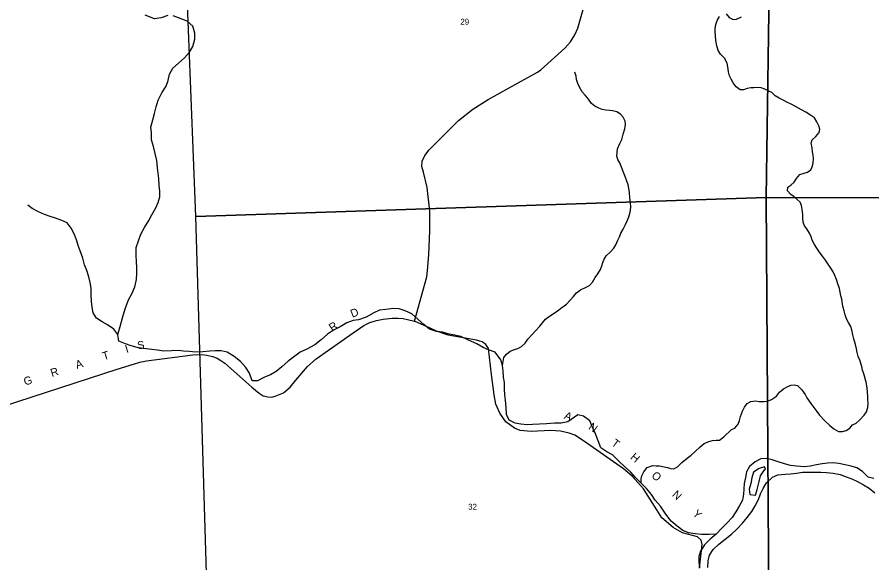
# Model space of a CAD drawing. Extents: x 1312308 to 1684953, y 460642 to 865172.
# Drawn here: x 1414861 to 1422870, y 611344 to 616453 of the extents above; entities that cross this region are included whole.
import ezdxf

# ---------------------------------------------------------------- set-up
doc = ezdxf.new("R2010")
doc.units = 0
for name, color, linetype in [('GM_X_Major_River', 7, 'Continuous'), ('GM_X_Minor_River', 7, 'Continuous'), ('GM_X_Section', 7, 'Continuous'), ('GM_X_Section_Text', 7, 'Continuous'), ('GM_X_Township_Road', 7, 'Continuous'), ('GM_X_Township_Road_Text', 7, 'Continuous')]:
    doc.layers.add(name, color=color, linetype=linetype)

msp = doc.modelspace()

# ---------------------------------------------------------------- linework, layer by layer
at = {"layer": 'GM_X_Major_River'}
for points in [[(1422889, 612132.9), (1422835.2, 612146.1), (1422780.1, 612199.4), (1422728.7, 612234.6), (1422674.9, 612247.8), (1422619, 612261), (1422559.1, 612274.3), (1422505.1, 612281.5), (1422455, 612278.6), (1422404.7, 612271.7), (1422350.3, 612260.8), (1422291.9, 612248.1), (1422239.7, 612243.2), (1422163.6, 612248.9), (1422107.6, 612256.1), (1422049.7, 612269.4), (1421990, 612288.7), (1421936.3, 612307.9), (1421882.4, 612321.1), (1421830.2, 612316.2), (1421775.5, 612289.4), (1421722.5, 612246.4), (1421693.3, 612195), (1421684.2, 612143), (1421673, 612087.2), (1421667, 611987.1), (1421657.7, 611929.2), (1421626.5, 611873.8), (1421595.3, 611820.3), (1421560.2, 611769), (1421513, 611717.9), (1421461.8, 611666.9), (1421410.6, 611611.9), (1421355.5, 611565), (1421302.2, 611512), (1421263, 611454.8), (1421247.8, 611403), (1421248.7, 611348.9), (1421255.7, 611298.6)], [(1421332, 611301), (1421335.2, 611363), (1421348.4, 611416.8), (1421383.5, 611468.2), (1421436.7, 611519.1), (1421495.8, 611565.9), (1421553, 611612.8), (1421604, 611657.8), (1421657.4, 611716.8), (1421702.5, 611767.9), (1421745.8, 611825.1), (1421777, 611876.5), (1421806.3, 611936), (1421827.4, 611989.6), (1421850.5, 612041.2), (1421883.7, 612092.6), (1421936.9, 612145.6), (1421989.5, 612166.5), (1422055.8, 612173.1), (1422106, 612176), (1422162.2, 612182.8), (1422218.6, 612191.6), (1422270.7, 612192.4), (1422328.9, 612193.2), (1422391, 612193.8), (1422443.1, 612190.7), (1422507.1, 612183.3), (1422571, 612169.9)], [(1421862.7, 612243.4), (1421812.3, 612226.4), (1421761.4, 612191.5), (1421746.3, 612139.7), (1421735.2, 612087.8), (1421720.1, 612034.1), (1421727, 611983.8), (1421779.1, 611978.7), (1421796.2, 612030.4), (1421798.5, 612044.4)], [(1421798.5, 612044.4), (1421813.8, 612106.2), (1421826.9, 612160), (1421864.1, 612213.3), (1421872.3, 612221.1)], [(1421872.3, 612221.1), (1421862.7, 612243.4)], [(1422571, 612169.9), (1422628.7, 612150.6), (1422682.4, 612129.4), (1422734.1, 612106.2), (1422789.6, 612074.9), (1422843.1, 612043.7), (1422896.3, 611998.5)]]:
    msp.add_lwpolyline(points, dxfattribs=at)
at = {"layer": 'GM_X_Minor_River'}
for points in [[(1416122.7, 613340.6), (1416042.7, 613351.2), (1415986.7, 613361.1), (1415931, 613377), (1415875.3, 613394.8), (1415813.8, 613418.9), (1415805.7, 613481.4), (1415826.1, 613555), (1415848.7, 613636.6), (1415873.5, 613722.1), (1415904.3, 613807.4), (1415938.3, 613868.5), (1415964.3, 613927.9), (1415980.4, 613995.6), (1415984.3, 614055.7), (1415981.9, 614105.9), (1415979.7, 614166.2), (1415975.5, 614222.6), (1415975.7, 614294.8), (1416021.8, 614419.8), (1416055.9, 614482.9), (1416094.1, 614547.9), (1416123.9, 614603.2), (1416160, 614666.2), (1416181.7, 614717.7), (1416197.4, 614769.4), (1416197.1, 614823.6), (1416192.8, 614878), (1416188.7, 614942.3), (1416175.8, 615043.1), (1416169.9, 615111.6), (1416155.9, 615176.3), (1416137.9, 615243.1), (1416121.7, 615303.9), (1416119.8, 615370.2), (1416113.4, 615422.6), (1416131.5, 615490.3), (1416147.5, 615550), (1416163.5, 615611.8), (1416183.5, 615675.3), (1416217.8, 615744.5), (1416257.9, 615805.4), (1416277.7, 615861), (1416289.5, 615918.9), (1416321.4, 615974), (1416373.1, 616022.6), (1416428.9, 616072.9), (1416476.7, 616123.6), (1416508.5, 616176.8), (1416526.7, 616246.5), (1416526.4, 616302.7), (1416506.4, 616367.6), (1416455.7, 616415.5), (1416374.3, 616446.2), (1416322.7, 616466)], [(1416272.5, 616467.6), (1416209.6, 616445.6), (1416149, 616435.5), (1416059.7, 616470.6)], [(1422406.5, 614213.7), (1422385.1, 614244.2), (1422354, 614291), (1422330.6, 614325.5), (1422311.3, 614364), (1422302, 614396.3), (1422284.6, 614430.8), (1422259.3, 614469.4), (1422237.9, 614499.9), (1422226.5, 614532.2), (1422221.4, 614574.5), (1422222, 614604.6), (1422216.9, 614650.8), (1422209.7, 614689.1), (1422196.3, 614721.5), (1422141.1, 614770.7), (1422111.5, 614791.3), (1422078.1, 614828.1), (1422080.8, 614860.1), (1422111.3, 614879.6), (1422140, 614909.2), (1422164.7, 614942.9), (1422193.5, 614978.5), (1422233.9, 614991.8), (1422266.2, 615001.2), (1422298.7, 615022.7), (1422309.4, 615052.6), (1422318.1, 615086.6), (1422321, 615128.7), (1422319.6, 615160.8), (1422314.2, 615191), (1422309, 615229.3), (1422299.9, 615273.6), (1422310.6, 615305.6), (1422345.3, 615335), (1422374.1, 615372.6), (1422380.8, 615402.6), (1422371.4, 615434.9), (1422354.1, 615473.4), (1422332.8, 615509.9), (1422293.2, 615534.8), (1422251.6, 615561.6), (1422210, 615584.5), (1422154.5, 615615.6), (1422112.8, 615636.5), (1422073, 615655.3), (1422043.3, 615671.9), (1422001.6, 615694.7), (1421963.9, 615715.5), (1421932.5, 615748.2), (1421902.7, 615760.8), (1421865, 615779.6), (1421831.1, 615790.2), (1421797, 615792.9), (1421764.9, 615789.5), (1421734.8, 615790), (1421702.6, 615784.6), (1421666.2, 615771.2), (1421636.1, 615771.8), (1421598.6, 615800.6), (1421571.3, 615837.2), (1421549.9, 615871.8), (1421536.5, 615902.1), (1421525.3, 615940.5), (1421520.2, 615986.8), (1421512.9, 616023), (1421489.8, 616069.6), (1421452.5, 616106.5), (1421429.1, 616141), (1421418, 616185.4), (1421408.9, 616233.8), (1421403.9, 616280), (1421400.5, 616314.2), (1421401.2, 616344.3), (1421408, 616384.3), (1421420.8, 616420.3), (1421441.7, 616460)], [(1421504.3, 616485), (1421533.7, 616450.3), (1421569.4, 616429.6), (1421599.6, 616433), (1421648.1, 616454.2)], [(1419409.7, 613190.9), (1419420.4, 613267.4), (1419447.1, 613297), (1419481.8, 613326.4), (1419522.2, 613339.8), (1419552.5, 613351.2), (1419587, 613368.7), (1419619.7, 613400.2), (1419646.6, 613437.8), (1419683.5, 613479.3), (1419757.4, 613558.2), (1419784.1, 613589.8), (1419812.9, 613625.4), (1419849.6, 613654.8), (1419884.2, 613676.3), (1419922.8, 613703.7), (1419965.6, 613733), (1420008.4, 613766.3), (1420043.2, 613801.8), (1420074, 613837.4), (1420102.8, 613873), (1420139.4, 613898.4), (1420192.1, 613923.5), (1420222.5, 613939), (1420251.3, 613970.6), (1420278.3, 614016.3), (1420303, 614049.9), (1420325.9, 614091.7), (1420338.7, 614125.5), (1420349.3, 614155.5), (1420362, 614187.3), (1420380.7, 614217.1), (1420421.6, 614256.5), (1420452.4, 614290), (1420469.1, 614321.9), (1420488, 614363.7), (1420504.7, 614397.5), (1420517.4, 614429.4), (1420540.2, 614467.1), (1420561.3, 614512.9), (1420580.1, 614552.7), (1420592.8, 614584.5), (1420605.7, 614626.5), (1420610.7, 614674.5), (1420607.6, 614716.8), (1420602.4, 614761), (1420599.5, 614811.3), (1420592.3, 614851.5), (1420584.9, 614883.8), (1420573.5, 614916.1), (1420558.4, 614960.6), (1420539.3, 615009.1), (1420524.1, 615047.5), (1420506.9, 615088), (1420489.5, 615120.4), (1420480.1, 615152.7), (1420487.5, 615218.8), (1420508.6, 615270.6), (1420525.4, 615308.5), (1420540.5, 615358.4), (1420553.5, 615406.3), (1420560.3, 615446.4), (1420557, 615478.5), (1420539.7, 615515), (1420514.2, 615545.6), (1420478.6, 615566.3), (1420440.6, 615575), (1420410.6, 615577.6), (1420376.6, 615582.2), (1420342.6, 615588.9), (1420310.8, 615601.5), (1420273.1, 615620.3), (1420241.5, 615645), (1420214.2, 615685.6), (1420182.9, 615722.3), (1420155.4, 615753), (1420130.3, 615797.6), (1420114.9, 615830), (1420103.6, 615868.4), (1420098.3, 615900.6), (1420087, 615936.9)], [(1415805.7, 613481.4), (1415768.3, 613531.5), (1415709, 613572.8), (1415657.4, 613600), (1415606, 613635.2), (1415575, 613685.9), (1415564, 613738.3), (1415559.1, 613790.5), (1415556.5, 613856.7), (1415553.7, 613916.9), (1415544.8, 613969.2), (1415531.8, 614021.6), (1415513, 614082.1), (1415494, 614134.7), (1415477.3, 614197.2), (1415450.6, 614263.9), (1415433.6, 614314.4), (1415418.7, 614366.8), (1415399.7, 614417.3), (1415368.8, 614476.1), (1415331.8, 614527), (1415280.1, 614550.2), (1415222.4, 614569.5), (1415170.6, 614586.6), (1415116.9, 614605.8), (1415061.2, 614631.1), (1415001.7, 614662.4), (1414960.3, 614693.4)], [(1420706.9, 612088.6), (1420709, 612129.8), (1420715.6, 612159.7), (1420734.4, 612197.5), (1420765.3, 612237.1), (1420817.9, 612256.2), (1420847.9, 612253.6), (1420879.9, 612251), (1420921.9, 612244.2), (1420953.8, 612235.6), (1420983.7, 612227), (1421013.8, 612224.5), (1421048.3, 612243.9), (1421089.2, 612283.3), (1421138.1, 612322.5), (1421174.9, 612351.9), (1421213.7, 612387.3), (1421260.7, 612430.6), (1421299.4, 612460), (1421342, 612481.3), (1421376.2, 612488.7), (1421410.4, 612492.1), (1421440.5, 612493.5), (1421483.3, 612522.8), (1421554.9, 612591.7), (1421585.2, 612605.2), (1421616.1, 612640.8), (1421628.8, 612676.7), (1421637.6, 612714.6), (1421658.7, 612764.4), (1421675.5, 612802.2), (1421702.3, 612835.8), (1421736.8, 612855.3), (1421779, 612860.5), (1421815, 612855.8), (1421859.1, 612853), (1421891.3, 612858.4), (1421927.7, 612871.8), (1421974.5, 612905.1), (1422003.3, 612940.7), (1422042.1, 612972), (1422074.6, 612991.5), (1422109, 613006.9), (1422141.1, 613010.3), (1422171.1, 613003.8), (1422212.4, 612964.9), (1422243.6, 612920.1), (1422261, 612889.7), (1422298, 612834.8), (1422325.3, 612798.2), (1422354.6, 612759.5), (1422380, 612726.9), (1422429.1, 612673.8), (1422474.3, 612628.9), (1422513.8, 612598), (1422557.5, 612575.1), (1422593.5, 612572.5), (1422629.8, 612581.8), (1422662.3, 612603.3), (1422689.1, 612634.9), (1422721.5, 612652.4), (1422756.3, 612683.8), (1422797.2, 612725.2), (1422820, 612756.9), (1422830.8, 612796.8), (1422833.7, 612838.9), (1422832.3, 612871.1), (1422830.9, 612901.2), (1422829.7, 612941.4), (1422826.6, 612983.6), (1422815.6, 613033.9), (1422793.2, 613114.7), (1422781.9, 613149), (1422774.5, 613183.2), (1422757.7, 613241.8), (1422742.3, 613274.2), (1422733.1, 613314.5), (1422725.8, 613348.7), (1422716.6, 613389), (1422701.6, 613441.5), (1422692.4, 613479.8), (1422683.2, 613524.1), (1422671.9, 613556.5), (1422654.5, 613588.9), (1422633.2, 613629.4), (1422619.9, 613665.8), (1422610.7, 613704.1), (1422599.3, 613734.4), (1422593.9, 613766.7), (1422586.9, 613812.9), (1422579.5, 613843.2), (1422572.1, 613877.5), (1422564.9, 613913.7), (1422551.7, 613956.1), (1422538.5, 613996.5), (1422523.2, 614034.9), (1422505.9, 614069.4), (1422484.5, 614103.9), (1422461.2, 614140.5), (1422433.9, 614179.1), (1422406.5, 614213.7)], [(1421410.6, 611611.9), (1421344.7, 611610.1), (1421274.4, 611610.4), (1421214.3, 611614.4), (1421152.4, 611626.4), (1421096.8, 611646.3), (1421045.9, 611688.1), (1420989.1, 611734.1), (1420938.9, 611800), (1420889, 611873.9), (1420840.5, 611929.7), (1420804, 611983.1), (1420757.6, 612038.8), (1420706.9, 612088.6), (1420656.4, 612142.4), (1420611.8, 612194.1), (1420551.1, 612246.3), (1420500.4, 612294.1), (1420438, 612354.3), (1420386.7, 612382.1), (1420329.7, 612422.1), (1420281.5, 612552.2), (1420253.3, 612613.3), (1420227, 612672.4), (1420168.2, 612718.4), (1420114.4, 612730.2), (1420021.9, 612663), (1419959.3, 612651), (1419895, 612651.1), (1419822.5, 612645.5), (1419689.7, 612637.8), (1419639.5, 612637.4), (1419579.4, 612643.4), (1419527.5, 612653.1), (1419470.1, 612679.1), (1419445.6, 612732.1), (1419441.7, 612798.4), (1419437.8, 612866.8), (1419431.3, 612917.2), (1419426.9, 612969.5), (1419428.9, 613031.7), (1419418.4, 613082.2), (1419416.2, 613140.5), (1419409.7, 613190.9), (1419393.4, 613245.6), (1419339.3, 613315.7), (1419277.7, 613337.8), (1419226.3, 613361.5), (1419169.1, 613395.5), (1419091.8, 613430.1), (1419018.5, 613462.7), (1418962.7, 613474.5), (1418908.8, 613484.3), (1418847.1, 613502.4), (1418791, 613508.2), (1418725.4, 613530.5), (1418670.6, 613574.4), (1418617.8, 613622.3), (1418559.2, 613674.4), (1418495.9, 613704.6), (1418440.1, 613720.4), (1418386.1, 613726.2), (1418315.4, 613714.5), (1418257, 613708.4), (1418204, 613684), (1418130.5, 613644.3), (1418059.4, 613620.5), (1418009, 613612.1), (1417950.1, 613591.9), (1417888.7, 613553.8), (1417825.4, 613521.8), (1417770, 613485.4), (1417710.1, 613431.2), (1417650.4, 613385), (1417574.9, 613345.3), (1417511.7, 613317.2), (1417452, 613269), (1417400.6, 613230.6), (1417340.7, 613178.3), (1417287.1, 613133.9), (1417236, 613105.5), (1417179.1, 613083.2), (1417113.7, 613049.3), (1417063.5, 613046.9), (1417039.6, 613119.9), (1417005.1, 613173.2), (1416952.7, 613229.2), (1416895.9, 613277.2), (1416828.8, 613315.5), (1416773, 613327.3), (1416718.8, 613329.1), (1416666.5, 613326.8), (1416600, 613319), (1416533.6, 613315.1), (1416477.6, 613323), (1416421.5, 613326.8), (1416369.4, 613330.5), (1416307.1, 613328.5), (1416234.7, 613326.9), (1416176.7, 613334.8), (1416122.7, 613340.6)]]:
    msp.add_lwpolyline(points, dxfattribs=at)
at = {"layer": 'GM_X_Section'}
for points in [[(1416340.1, 619587.9), (1421948.9, 619535.5), (1421880.4, 614765), (1416536.6, 614585.6)], [(1421948.9, 619535.5), (1426939.4, 619468.3), (1427084.1, 614755.3), (1421880.4, 614765)], [(1421880.4, 614765), (1421912, 609528.3), (1416727.1, 609575.6), (1416685.1, 609576.5), (1416536.6, 614585.6)], [(1427084.1, 614755.3), (1427288.4, 609459), (1422083.8, 609518.6), (1421912, 609528.3), (1421880.4, 614765)]]:
    msp.add_lwpolyline(points, close=True, dxfattribs=at)
at = {"layer": 'GM_X_Township_Road'}
for points in [[(1418708.7, 614113.9), (1418718.6, 614229.7), (1418729.2, 614451.6), (1418728.1, 614637.4), (1418703.7, 614858.3), (1418667.6, 615002.6), (1418654.2, 615055.6), (1418657, 615103.5), (1418682.5, 615158.7), (1418721.8, 615209.7), (1418997.8, 615485.7), (1419131.1, 615590.9), (1419274.4, 615682.7), (1419554.7, 615838.8), (1419735.7, 615938.6), (1419768.9, 615958.5), (1419992.7, 616163.7), (1420046.3, 616222.1), (1420086.6, 616286.3), (1420113.4, 616348), (1420182.4, 616589.3), (1420339.8, 617133)], [(1418431.1, 613633.3), (1418477.4, 613632.9), (1418584.8, 613607.4), (1418699.5, 614020.5), (1418705.8, 614080), (1418708.7, 614113.9)], [(1414595.5, 612765.6), (1415798.5, 613157.3), (1415950.4, 613204.8), (1416012.6, 613222.9), (1416073.1, 613235.9), (1416507.5, 613291.1), (1416592.1, 613293.7), (1416637.8, 613288.5), (1416690.5, 613274.7), (1416734.6, 613258.7), (1416770, 613239.3), (1416807.1, 613213.4), (1417061, 612989.3), (1417130.5, 612932.8), (1417165.1, 612906), (1417209.6, 612897.6), (1417246.2, 612896), (1417279.5, 612904.7), (1417356.4, 612935.4), (1417419.4, 612988), (1417472.9, 613052.8), (1417581.1, 613183.1), (1417661.7, 613253.3), (1418009.4, 613496), (1418108.9, 613566.9), (1418164.6, 613593.9), (1418227.5, 613613.8), (1418291.9, 613625.7), (1418375.5, 613633.7), (1418431.1, 613633.3)], [(1421255.9, 611295.6), (1421278.4, 611517.2), (1421269.6, 611556), (1421235.8, 611587.3), (1421094.9, 611624.3), (1421009.2, 611673.7), (1420902.8, 611766.3), (1420853.9, 611841.5), (1420730, 612038), (1420622.3, 612154.5), (1420540.9, 612223.3), (1420169.1, 612486.3), (1420086.4, 612540.1), (1420032.6, 612558.9), (1419951.2, 612576.4), (1419859.8, 612581.4), (1419677, 612573.9), (1419575.6, 612582.7), (1419520.5, 612604), (1419440.4, 612662.8), (1419384.1, 612745.4), (1419346.5, 612828.1), (1419330.2, 612918.2), (1419305.2, 613108.5), (1419276.4, 613350.4), (1419253.3, 613387), (1419219.1, 613414.1), (1419166.6, 613430), (1418900, 613476.9), (1418790.1, 613514.3), (1418729.6, 613542.2), (1418584.8, 613607.4)]]:
    msp.add_lwpolyline(points, dxfattribs=at)

# ---------------------------------------------------------------- texts
at = {"layer": 'GM_X_Section_Text'}
for s, p in [('29', (1419014.4, 616382.2)), ('32', (1419087, 611841.4))]:
    msp.add_text(s, height=55.25, rotation=0.00001, dxfattribs=at).set_placement(p)
at = {"layer": 'GM_X_Township_Road_Text'}
for s, rotation, p in [('D', 22.07401, (1418002.1, 613637.8)), ('R', 34.45756, (1417814, 613506.5)), ('I', 16.76354, (1415885.8, 613308)), ('S', 8.79132, (1415993, 613341.1)), ('T', 17.76883, (1415673.4, 613240)), ('A', 17.84514, (1415422.2, 613159.1)), ('R', 17.84554, (1415187.7, 613083.6)), ('G', 17.84514, (1414936.4, 613002.7)), ('A', 336.87196, (1419979.3, 612696.6)), ('N', 324.89935, (1420207.6, 612600.9)), ('T', 324.28173, (1420422.9, 612449.6)), ('H', 319.55241, (1420599.9, 612322.7)), ('O', 317.26858, (1420798.5, 612153.5)), ('N', 317.21711, (1420992.3, 611974.4)), ('Y', 315.16228, (1421184, 611797.1))]:
    msp.add_text(s, height=75, rotation=rotation, dxfattribs=at).set_placement(p)

doc.saveas('drawing.dxf')
